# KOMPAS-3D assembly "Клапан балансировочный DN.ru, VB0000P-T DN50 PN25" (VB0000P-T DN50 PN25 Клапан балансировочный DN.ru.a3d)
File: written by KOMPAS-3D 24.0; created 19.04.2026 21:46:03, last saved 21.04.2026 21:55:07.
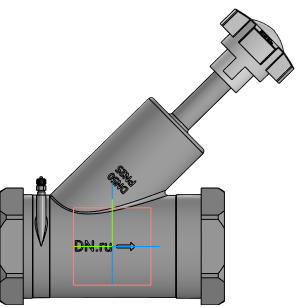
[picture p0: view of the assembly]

Document properties: Автор: DN.ru; Полное имя файла: C:\Работа\VB0000P-T DN X PN 25 Клапан балансировочный DN.ru\DN50\исходные материалы\VB0000P-T DN50 PN25 Клапан балансировочный DN.ru.a3d

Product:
- Component [detail]: Деталь  | qty 1  | pos. 1  | Масса: 0.00084; Раздел спецификации: Прочие изделия; Примечание: D080-01177; Автор: mrdid; source file: VB0000P-T DN50 PN25 Клапан балансировочный DN.ru.m3d
- Component [detail]: Деталь2  | qty 1  | pos. 2  | Масса: 0.358794; Автор: tyuri; additional columns: Типовые; source file: Деталь2 - Деталь2.m3d
- Part/product: Клапан балансировочный DN.ru  | designation VB0000P-T DN50 PN25
    Масса: 1.9
    Раздел спецификации: Прочие изделия
    Примечание: D080-01180

Referenced files in C:\Работа\VB0000P-T DN X PN 25 Клапан балансировочный DN.ru\DN50\исходные материалы\: Деталь2 - Деталь2.m3d, VB0000P-T DN50 PN25 Клапан балансировочный DN.ru.m3d
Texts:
  VB0000P-T DN50 PN25
  Деталь2 Деталь2
  Плоскость XY.Начало координат
  Плоскость ZY.Начало координат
